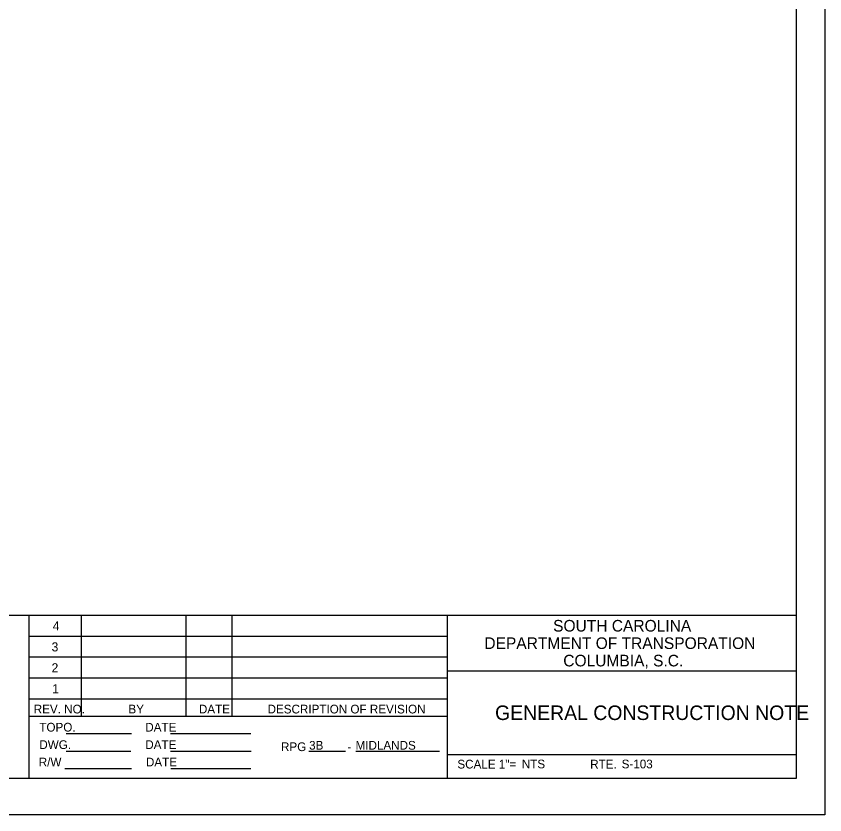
# Model space of a CAD drawing. Extents: x 8134 to 11793, y 3225 to 13425.
# Drawn here: x 11221 to 11777, y 5500 to 6050 of the extents above; entities that cross this region are included whole.
import ezdxf

# ---------------------------------------------------------------- set-up
doc = ezdxf.new("R2010")
doc.units = 0
for name, color, linetype in [('RD_SHT_Bndy', 7, 'Continuous'), ('RD_SHT_IplotShp', 7, 'Continuous'), ('RD_SHT_TX', 7, 'Continuous')]:
    doc.layers.add(name, color=color, linetype=linetype)

msp = doc.modelspace()

# ---------------------------------------------------------------- linework, layer by layer
at = {"layer": 'RD_SHT_Bndy'}
for p, q in [((10995.01, 5637.45), (11757.6, 5637.45)), ((11229.59, 5525), (11229.59, 5637.45)), ((11229.59, 5637.45), (11229.59, 5637.45)), ((11265.59, 5567.76), (11265.59, 5637.45)), ((11337.59, 5567.76), (11337.59, 5637.45)), ((11369.41, 5567.9), (11369.41, 5637.5)), ((11517.59, 5525), (11517.59, 5637.45)), ((11229.59, 5623.1), (11517.59, 5623.1)), ((11229.59, 5608.7), (11517.59, 5608.7)), ((11517.59, 5599.1), (11757.6, 5599.1)), ((11229.59, 5594.3), (11517.59, 5594.3)), ((11229.59, 5579.9), (11517.59, 5579.9)), ((11229.59, 5567.9), (11517.59, 5567.9)), ((11255.03, 5555.9), (11299.91, 5555.9)), ((11326.79, 5555.9), (11382.08, 5555.9)), ((11255.03, 5543.9), (11299.52, 5543.9)), ((11326.79, 5543.9), (11382.51, 5543.9)), ((11422.11, 5543.9), (11447.32, 5543.9)), ((11454.51, 5543.9), (11512.02, 5543.9)), ((11517.59, 5541.5), (11757.6, 5541.5)), ((11254.21, 5531.9), (11299.91, 5531.9)), ((11327.17, 5531.9), (11382.08, 5531.9)), ((11760, 5500), (10000, 5500)), ((11760, 5500), (10000, 5500))]:
    msp.add_line(p, q, dxfattribs=at)
msp.add_lwpolyline([(10082.6, 6575), (11757.6, 6575), (11757.6, 5525), (10082.6, 5525)], close=True, dxfattribs=at)
at = {"layer": 'RD_SHT_IplotShp'}
msp.add_lwpolyline([(9981.4, 6600), (11777.4, 6600), (11777.4, 5500), (9981.4, 5500)], close=True, dxfattribs=at)

# ---------------------------------------------------------------- texts
at = {"layer": 'RD_SHT_TX'}
for s, height, p in [('4', 6.24, (11245.76, 5626.94)), ('SOUTH CAROLINA', 8, (11590.31, 5626.21)), ('3', 6.24, (11244.99, 5612.54)), ('DEPARTMENT OF TRANSPORATION', 8, (11542.97, 5614.21)), ('COLUMBIA, S.C.', 8, (11597.31, 5602.21)), ('2', 6.24, (11244.99, 5598.14)), ('1', 6.24, (11245.38, 5583.74)), ('REV. NO.', 6, (11232.71, 5569.82)), ('BY', 6, (11297.89, 5569.82)), ('DATE', 6, (11346.42, 5569.82)), ('DESCRIPTION OF REVISION', 6, (11393.7, 5569.82)), ('   GENERAL CONSTRUCTION NOTE   ', 10, (11539.2, 5565.3)), ('TOPO.', 6, (11236.55, 5557.34)), ('DATE', 6, (11309.51, 5557.34)), ('DWG.', 6, (11236.55, 5545.34)), ('DATE', 6, (11309.51, 5545.34)), ('RPG', 6, (11402.96, 5543.9)), ('3B    ', 6, (11422.31, 5544.88)), ('-', 6, (11448.7, 5543.9)), ('MIDLANDS   ', 6, (11454.29, 5544.88)), ('R/W', 6, (11236.16, 5533.34)), ('DATE', 6, (11309.94, 5533.34)), ('SCALE 1"=', 6, (11524.4, 5531.9)), ('NTS        ', 6, (11568.76, 5532.01)), ('RTE.', 6, (11615.84, 5531.9)), ('S-103      ', 6, (11637.49, 5532.01))]:
    msp.add_text(s, height=height, dxfattribs=at).set_placement(p)

doc.saveas('drawing.dxf')
